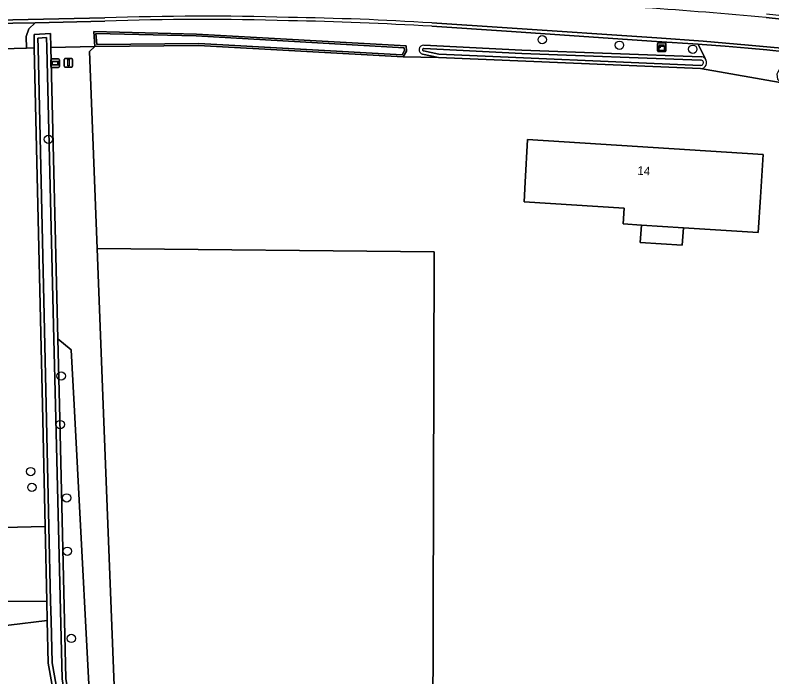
# Model space of a CAD drawing. Extents: x 162510 to 163918, y 388494 to 389774.
# Drawn here: x 162767.9 to 162856.6, y 388968.2 to 389045.6 of the extents above; entities that cross this region are included whole.
import ezdxf

# ---------------------------------------------------------------- set-up
doc = ezdxf.new("R2010")
doc.units = 0
for name, color, linetype in [('IMGEO_Afsluitpaal', 7, 'Continuous'), ('IMGEO_Boom', 7, 'Continuous'), ('IMGEO_Erf', 7, 'Continuous'), ('IMGEO_Grasland_agrarisch', 7, 'Continuous'), ('IMGEO_Grasland_overig', 7, 'Continuous'), ('IMGEO_Groenvoorziening', 7, 'Continuous'), ('IMGEO_Hek', 7, 'Continuous'), ('IMGEO_Informatiebord', 7, 'Continuous'), ('IMGEO_Kast', 7, 'Continuous'), ('IMGEO_Loofbos', 7, 'Continuous'), ('IMGEO_Oever', 7, 'Continuous'), ('IMGEO_Pand', 7, 'Continuous'), ('IMGEO_Pand_nummerreeks', 7, 'Continuous'), ('IMGEO_Rijbaan_lokaal_gesloten', 7, 'Continuous'), ('IMGEO_Rijbaan_lokaal_halfverhard', 7, 'Continuous'), ('IMGEO_Rijbaan_lokaal_open', 7, 'Continuous'), ('IMGEO_Voetpad_halfverhard', 7, 'Continuous'), ('IMGEO_Waterloop', 7, 'Continuous')]:
    doc.layers.add(name, color=color, linetype=linetype)

msp = doc.modelspace()

# ---------------------------------------------------------------- linework, layer by layer
at = {"layer": 'IMGEO_Afsluitpaal'}
for p, q in [((162773.667, 389039.666), (162773.667, 389040.466)), ((162773.667, 389040.466), (162773.667, 389039.666)), ((162773.767, 389040.566), (162774.557, 389040.566)), ((162774.557, 389040.566), (162773.767, 389040.566)), ((162774.657, 389040.466), (162774.657, 389039.666)), ((162774.657, 389039.666), (162774.657, 389040.466)), ((162774.557, 389039.566), (162773.767, 389039.566)), ((162773.767, 389039.566), (162774.557, 389039.566))]:
    msp.add_line(p, q, dxfattribs=at)
msp.add_lwpolyline([(162774.087, 389040.441), (162774.237, 389040.441), (162774.237, 389039.691), (162774.087, 389039.691), (162774.087, 389040.441)], dxfattribs=at)
for centre, start, end in [((162773.767, 389040.466), 90, 180), ((162773.767, 389040.466), 90, 180), ((162774.557, 389040.466), 0, 90), ((162774.557, 389040.466), 360, 90), ((162773.767, 389039.666), 180, 270), ((162773.767, 389039.666), 180, 270), ((162774.557, 389039.666), 270, 0), ((162774.557, 389039.666), 270, 0)]:
    msp.add_arc(centre, 0.1, start, end, dxfattribs=at)
at = {"layer": 'IMGEO_Boom'}
for centre in [(162829.664, 389042.769), (162838.704, 389042.119), (162847.288, 389041.648), (162771.825, 389031.101), (162773.319, 389003.39), (162773.212, 388997.705), (162769.744, 388992.197), (162769.896, 388990.351), (162773.96, 388989.12), (162774.038, 388982.866), (162774.507, 388972.654)]:
    msp.add_circle(centre, 0.489, dxfattribs=at)
at = {"layer": 'IMGEO_Erf'}
for points in [[(162770.174, 389041.798), (162769.256, 389041.776), (162764.939, 389041.674), (162762.366, 389041.613), (162743.97, 389041.227), (162741.471, 389041.257), (162723.167, 389042.732), (162708.724, 389044.447), (162703.427, 389045.076), (162701.259, 389045.333), (162703.968, 389013.408), (162704.722, 389000), (162705.649, 388983.517), (162705.816, 388981.677), (162713.87, 388982.43), (162742.1, 388985.07), (162771.437, 388985.756), (162771.116, 389000)], [(162904.759, 389000), (162888.657, 389027.915), (162878.247, 389034.159), (162876.77, 389034.586), (162858.205, 389037.636), (162848.201, 389039.379), (162817.501, 389040.674), (162813.372, 389040.745), (162789.42, 389042.091), (162777.269, 389041.966), (162776.653, 389041.374), (162777.546, 389018.317), (162817.007, 389017.924), (162816.849, 388961.047), (162821.19, 388960.918), (162824.385, 388960.757), (162843.871, 388960.067), (162877.142, 388962.939), (162916.429, 388980.385)], [(162841.136, 389019.015), (162841.267, 389021.061), (162839.13, 389021.198), (162839.248, 389023.043), (162827.528, 389023.793), (162827.657, 389026.081), (162827.938, 389031.073), (162855.524, 389029.307), (162855.205, 389024.318), (162854.94, 389020.186), (162846.185, 389020.746), (162846.054, 389018.7)]]:
    msp.add_lwpolyline(points, close=True, dxfattribs=at)
at = {"layer": 'IMGEO_Grasland_agrarisch'}
msp.add_lwpolyline([(162777.546, 389018.317), (162778.255, 389000), (162779.719, 388962.152), (162816.849, 388961.047), (162817.007, 389017.924)], close=True, dxfattribs=at)
at = {"layer": 'IMGEO_Grasland_overig'}
msp.add_lwpolyline([(162779.719, 388962.152), (162778.255, 389000), (162777.546, 389018.317), (162776.653, 389041.374), (162777.269, 389041.966), (162772.097, 389041.844), (162772.922, 389007.728), (162774.501, 389006.451), (162774.839, 389000), (162777.135, 388956.129)], dxfattribs=at)
msp.add_lwpolyline([(162771.633, 388977.032), (162759.184, 388976.938), (162753.184, 388975.82), (162748.589, 388977.359), (162730.504, 388976.949), (162720.368, 388977.674), (162713.87, 388982.43), (162705.816, 388981.677), (162706.857, 388970.231), (162716.693, 388972.407), (162727.932, 388973.185), (162739.949, 388975.001), (162750.237, 388972.839), (162767.182, 388974.223), (162771.685, 388974.742)], close=True, dxfattribs=at)
at = {"layer": 'IMGEO_Groenvoorziening'}
for points in [[(162778.415, 389044.929), (162770.277, 389044.748), (162769.539, 389044.044), (162769.222, 389043.146), (162769.256, 389041.776), (162770.174, 389041.798), (162770.138, 389043.388), (162772.057, 389043.509), (162772.097, 389041.844), (162777.269, 389041.966), (162777.137, 389043.718), (162789.155, 389043.43), (162813.716, 389042.039), (162813.778, 389041.439), (162813.372, 389040.745), (162817.501, 389040.674), (162815.652, 389041.077)], [(162847.925, 389042.23), (162843.038, 389042.569), (162825.482, 389043.773), (162816.712, 389044.334)], [(162815.795, 389042.121), (162827.275, 389041.548), (162848.283, 389040.772)], [(162848.735, 389040.554), (162847.925, 389042.23)]]:
    msp.add_lwpolyline(points, dxfattribs=at)
for points in [[(162777.135, 388956.129), (162774.839, 389000), (162774.501, 389006.451), (162772.922, 389007.728), (162773.109, 389000), (162773.884, 388967.966), (162775.533, 388957.514)], [(162713.87, 388982.43), (162720.368, 388977.674), (162730.504, 388976.949), (162748.589, 388977.359), (162753.184, 388975.82), (162759.184, 388976.938), (162771.633, 388977.032), (162771.437, 388985.756), (162742.1, 388985.07)]]:
    msp.add_lwpolyline(points, close=True, dxfattribs=at)
for centre, radius, start, end in [((162790.017, 388719.927), 325.209, 88.248, 92.04453), ((162793.028, 388650.14), 394.905, 86.5617, 88.99422), ((162815.765, 389041.593), 0.529, 86.70574, 257.69536), ((162848.225, 389040.074), 0.7, 43.24558, 85.25831)]:
    msp.add_arc(centre, radius, start, end, dxfattribs=at)
at = {"layer": 'IMGEO_Hek'}
msp.add_lwpolyline([(162774.501, 389006.451), (162774.839, 389000), (162777.135, 388956.129)], dxfattribs=at)
at = {"layer": 'IMGEO_Informatiebord'}
for p, q in [((162772.116, 389039.613), (162772.116, 389040.413)), ((162772.116, 389040.413), (162772.116, 389039.613)), ((162772.216, 389040.513), (162773.006, 389040.513)), ((162773.006, 389040.513), (162772.216, 389040.513)), ((162773.106, 389040.413), (162773.106, 389039.613)), ((162773.106, 389039.613), (162773.106, 389040.413)), ((162773.006, 389039.513), (162772.216, 389039.513)), ((162772.216, 389039.513), (162773.006, 389039.513))]:
    msp.add_line(p, q, dxfattribs=at)
for points in [[(162772.217, 389040.245), (162773.005, 389040.245), (162773.005, 389039.781), (162772.217, 389039.781), (162772.217, 389040.245)], [(162772.282, 389040.18), (162772.282, 389039.846), (162772.94, 389039.846), (162772.94, 389040.18), (162772.282, 389040.18)]]:
    msp.add_lwpolyline(points, dxfattribs=at)
for centre, start, end in [((162772.216, 389040.413), 90, 180), ((162772.216, 389040.413), 90, 180), ((162773.006, 389040.413), 0, 90), ((162773.006, 389040.413), 360, 90), ((162772.216, 389039.613), 180, 270), ((162772.216, 389039.613), 180, 270), ((162773.006, 389039.613), 270, 0), ((162773.006, 389039.613), 270, 0)]:
    msp.add_arc(centre, 0.1, start, end, dxfattribs=at)
at = {"layer": 'IMGEO_Kast'}
for p, q in [((162843.153, 389041.46), (162843.153, 389042.301)), ((162843.153, 389042.301), (162843.153, 389041.46)), ((162843.228, 389042.385), (162844.069, 389042.385)), ((162844.069, 389042.385), (162843.228, 389042.385)), ((162844.153, 389042.31), (162844.153, 389041.469)), ((162844.153, 389041.469), (162844.153, 389042.31)), ((162844.078, 389041.385), (162843.237, 389041.385)), ((162843.237, 389041.385), (162844.078, 389041.385))]:
    msp.add_line(p, q, dxfattribs=at)
for points in [[(162843.348, 389042.175), (162843.948, 389042.175), (162843.948, 389042.09), (162843.348, 389042.09), (162843.348, 389042.175)], [(162843.348, 389042), (162843.948, 389042), (162843.948, 389041.511), (162843.348, 389041.511), (162843.348, 389042)]]:
    msp.add_lwpolyline(points, dxfattribs=at)
msp.add_circle((162843.432, 389041.849), 0.0377, dxfattribs=at)
for centre, start, end in [((162843.231, 389042.307), 92.4484, 184.28452), ((162843.231, 389042.307), 92.4484, 184.28452), ((162844.075, 389042.307), 2.4484, 94.28452), ((162844.075, 389042.307), 2.4484, 94.28452), ((162843.231, 389041.463), 182.4484, 274.28452), ((162843.231, 389041.463), 182.4484, 274.28452), ((162844.075, 389041.463), 272.4484, 4.28452), ((162844.075, 389041.463), 272.4484, 4.28452)]:
    msp.add_arc(centre, 0.0779, start, end, dxfattribs=at)
at = {"layer": 'IMGEO_Loofbos'}
msp.add_lwpolyline([(162717.28, 388932.34), (162727.745, 388932.578), (162735.9, 388933.723), (162744.349, 388936.06), (162752.379, 388937.208), (162755.764, 388937.153), (162759.98, 388935.891), (162774.27, 388930.052), (162780.166, 388928.645), (162779.729, 388931.614), (162777.312, 388948.038), (162777.418, 388954.513), (162773.993, 388957.606), (162771.797, 388969.757), (162771.685, 388974.742), (162767.182, 388974.223), (162750.237, 388972.839), (162739.949, 388975.001), (162727.932, 388973.185), (162716.693, 388972.407), (162706.857, 388970.231), (162708.895, 388947.83), (162711.59, 388931.691)], close=True, dxfattribs=at)
at = {"layer": 'IMGEO_Oever'}
for points in [[(162789.155, 389043.43), (162777.137, 389043.718), (162777.269, 389041.966), (162789.42, 389042.091), (162813.372, 389040.745), (162813.778, 389041.439), (162813.716, 389042.039)], [(162772.922, 389007.728), (162772.097, 389041.844), (162772.057, 389043.509), (162770.138, 389043.388), (162770.174, 389041.798), (162771.116, 389000), (162771.437, 388985.756), (162771.633, 388977.032), (162771.685, 388974.742), (162771.797, 388969.757), (162773.993, 388957.606), (162777.418, 388954.513), (162777.312, 388948.038), (162779.729, 388931.614), (162780.166, 388928.645), (162780.347, 388927.414), (162788.349, 388873.034), (162789.747, 388873.272), (162779.235, 388948.832), (162778.831, 388954.663), (162777.135, 388956.129), (162775.533, 388957.514), (162773.884, 388967.966), (162773.109, 389000)], [(162772.656, 388999.989), (162773.432, 388967.925), (162775.111, 388957.28), (162776.839, 388955.786), (162778.392, 388954.444), (162778.784, 388948.785), (162789.238, 388873.645), (162788.73, 388873.558), (162780.795, 388927.48), (162780.614, 388928.711), (162780.177, 388931.68), (162777.765, 388948.067), (162777.874, 388954.711), (162774.411, 388957.839), (162772.249, 388969.803), (162772.138, 388974.752), (162772.086, 388977.042), (162771.89, 388985.766), (162771.569, 389000.01), (162770.627, 389041.808), (162770.601, 389042.963), (162771.616, 389043.027), (162771.644, 389041.833), (162772.469, 389007.717)], [(162813.507, 389041.82), (162813.541, 389041.49), (162813.244, 389040.983), (162789.425, 389042.322), (162777.483, 389042.199), (162777.386, 389043.481), (162789.146, 389043.2)]]:
    msp.add_lwpolyline(points, close=True, dxfattribs=at)
for points in [[(162827.275, 389041.548), (162815.795, 389042.121)], [(162815.652, 389041.077), (162817.501, 389040.674), (162848.201, 389039.379)], [(162848.2, 389039.764), (162817.55, 389041.057), (162815.75, 389041.45), (162815.712, 389041.461)], [(162815.749, 389041.735), (162815.79, 389041.736), (162827.258, 389041.163), (162848.246, 389040.388)], [(162848.283, 389040.772), (162827.275, 389041.548)]]:
    msp.add_lwpolyline(points, dxfattribs=at)
for centre, radius, start, end in [((162815.765, 389041.593), 0.529, 86.70574, 257.69536), ((162815.765, 389041.593), 0.143, 96.45781, 248.16118), ((162848.224, 389040.076), 0.313, 265.54341, 86.02439), ((162848.225, 389040.077), 0.698, 268.0051, 43.11433), ((162848.225, 389040.074), 0.7, 43.24558, 85.25831)]:
    msp.add_arc(centre, radius, start, end, dxfattribs=at)
at = {"layer": 'IMGEO_Pand'}
for points in [[(162855.524, 389029.307), (162827.938, 389031.073), (162827.657, 389026.081), (162827.528, 389023.793), (162839.248, 389023.043), (162839.13, 389021.198), (162841.267, 389021.061), (162846.185, 389020.746), (162854.94, 389020.186), (162855.205, 389024.318)], [(162846.185, 389020.746), (162841.267, 389021.061), (162841.136, 389019.015), (162846.054, 389018.7)]]:
    msp.add_lwpolyline(points, close=True, dxfattribs=at)
at = {"layer": 'IMGEO_Rijbaan_lokaal_gesloten'}
for points in [[(162745.45, 389044.849), (162751.665, 389044.823), (162767.648, 389045.079), (162778.413, 389045.316)], [(162816.722, 389044.733), (162825.538, 389044.15), (162843.075, 389042.99), (162848.495, 389042.575), (162851.147, 389042.369), (162853.798, 389042.141), (162855.974, 389041.937), (162858.149, 389041.717), (162858.675, 389041.67), (162859.132, 389045.011), (162855.892, 389045.367)]]:
    msp.add_lwpolyline(points, dxfattribs=at)
for centre, radius, start, end in [((162796.463, 388392.876), 655.192, 84.795851, 86.040577), ((162790.006, 388712.842), 332.676, 88.29056, 91.99703), ((162795.328, 388702.417), 342.984, 86.42383, 89.23125)]:
    msp.add_arc(centre, radius, start, end, dxfattribs=at)
at = {"layer": 'IMGEO_Rijbaan_lokaal_halfverhard'}
for points in [[(162855.892, 389045.367), (162859.132, 389045.011), (162859.186, 389045.408), (162855.928, 389045.765)], [(162778.413, 389045.316), (162767.648, 389045.079), (162751.665, 389044.823), (162745.45, 389044.849)], [(162745.474, 389044.46), (162751.698, 389044.414), (162763.312, 389044.614), (162767.647, 389044.689), (162770.277, 389044.748), (162778.415, 389044.929)], [(162816.712, 389044.334), (162825.482, 389043.773), (162843.038, 389042.569), (162847.925, 389042.23), (162848.38, 389042.198), (162851.079, 389041.999), (162853.776, 389041.771), (162855.947, 389041.566), (162858.116, 389041.343), (162858.6, 389041.295), (162858.632, 389041.352), (162858.675, 389041.67), (162858.149, 389041.717), (162855.974, 389041.937), (162853.798, 389042.141), (162851.147, 389042.369), (162848.495, 389042.575), (162843.075, 389042.99), (162825.538, 389044.15), (162816.722, 389044.733)]]:
    msp.add_lwpolyline(points, dxfattribs=at)
for centre, radius, start, end in [((162796.463, 388392.876), 655.192, 84.795851, 86.040577), ((162790.006, 388712.842), 332.676, 88.29056, 91.99703), ((162790.017, 388719.927), 325.209, 88.248, 92.04453), ((162795.328, 388702.417), 342.984, 86.42383, 89.23125), ((162793.028, 388650.14), 394.905, 86.5617, 88.99422)]:
    msp.add_arc(centre, radius, start, end, dxfattribs=at)
at = {"layer": 'IMGEO_Rijbaan_lokaal_open'}
for points in [[(162858.6, 389041.295), (162858.116, 389041.343), (162855.947, 389041.566), (162853.776, 389041.771), (162851.079, 389041.999), (162848.38, 389042.198), (162847.925, 389042.23), (162848.735, 389040.554)], [(162848.201, 389039.379), (162858.205, 389037.636), (162857.434, 389037.893), (162857.256, 389038.096), (162857.179, 389038.771), (162857.307, 389039.01), (162858.6, 389041.295)]]:
    msp.add_lwpolyline(points, dxfattribs=at)
msp.add_arc((162848.225, 389040.077), 0.698, 268.0051, 43.11433, dxfattribs=at)
at = {"layer": 'IMGEO_Voetpad_halfverhard'}
msp.add_lwpolyline([(162769.539, 389044.044), (162770.277, 389044.748), (162767.647, 389044.689), (162763.312, 389044.614), (162764.221, 389043.664), (162764.909, 389042.849), (162764.939, 389041.674), (162769.256, 389041.776), (162769.222, 389043.146)], close=True, dxfattribs=at)
at = {"layer": 'IMGEO_Waterloop'}
for points in [[(162772.656, 388999.989), (162772.469, 389007.717), (162771.644, 389041.833), (162771.616, 389043.027), (162770.601, 389042.963), (162770.627, 389041.808), (162771.569, 389000.01), (162771.89, 388985.766), (162772.086, 388977.042), (162772.138, 388974.752), (162772.249, 388969.803), (162774.411, 388957.839), (162777.874, 388954.711), (162777.765, 388948.067), (162780.177, 388931.68), (162780.614, 388928.711), (162780.795, 388927.48), (162788.73, 388873.558), (162789.238, 388873.645), (162778.784, 388948.785), (162778.392, 388954.444), (162776.839, 388955.786), (162775.111, 388957.28), (162773.432, 388967.925)], [(162813.507, 389041.82), (162789.146, 389043.2), (162777.386, 389043.481), (162777.483, 389042.199), (162789.425, 389042.322), (162813.244, 389040.983), (162813.541, 389041.49)]]:
    msp.add_lwpolyline(points, close=True, dxfattribs=at)
for points in [[(162815.712, 389041.461), (162815.75, 389041.45), (162817.55, 389041.057), (162848.2, 389039.764)], [(162848.246, 389040.388), (162827.258, 389041.163), (162815.79, 389041.736), (162815.749, 389041.735)]]:
    msp.add_lwpolyline(points, dxfattribs=at)
for centre, radius, start, end in [((162815.765, 389041.593), 0.143, 96.45781, 248.16118), ((162848.224, 389040.076), 0.313, 265.54341, 86.02439)]:
    msp.add_arc(centre, radius, start, end, dxfattribs=at)

# ---------------------------------------------------------------- texts
at = {"layer": 'IMGEO_Pand_nummerreeks'}
msp.add_text('14', height=1, rotation=356.3388, dxfattribs=at).set_placement((162840.787, 389026.964))

doc.saveas('drawing.dxf')
